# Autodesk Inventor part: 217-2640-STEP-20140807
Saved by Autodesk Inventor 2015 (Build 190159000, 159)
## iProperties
Created: 2014-11
Part Number: 217-2640-STEP-20140807
Material: Generic
Document SubType Name: Modeling
Designer: User
Density: 1 g/cm^3
Appearance: Default
Author: User
Title: 217-2640-STEP-20140807.STEP
Description: STEP AP203
Creation Date: 2014-08-07
Sending System: SolidWorks 2014
Preprocessor: SwSTEP 2.0
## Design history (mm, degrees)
node "217-2640-STEP-201408071"
node "Chamfer2"
node "Base1"
